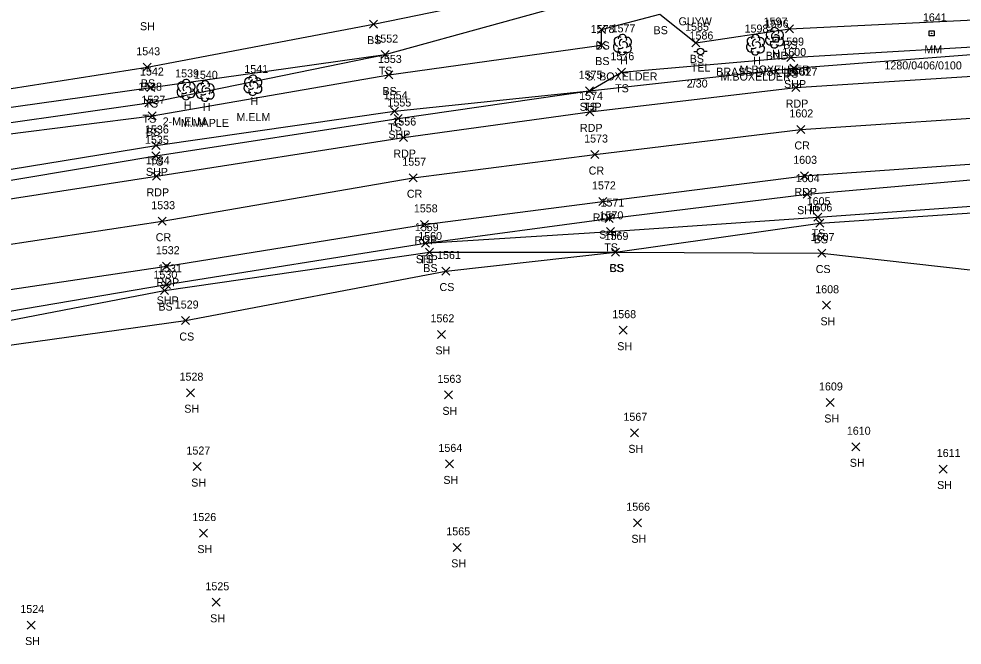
# Model space of a CAD drawing. Extents: x 1497084 to 1499861, y 734741 to 735567.
# Drawn here: x 1499123.3 to 1499358.9, y 735330.7 to 735487.1 of the extents above; entities that cross this region are included whole.
import ezdxf

# ---------------------------------------------------------------- set-up
doc = ezdxf.new("R2010")
doc.units = 0
for name, color, linetype in [('L_A', 7, 'Continuous'), ('L_C', 7, 'Continuous'), ('L_I', 7, 'Continuous'), ('L_TIC', 7, 'Continuous'), ('LELB', 7, 'Continuous'), ('LTD', 7, 'Continuous'), ('M_A', 7, 'Continuous'), ('M_C', 7, 'Continuous'), ('M_I', 7, 'Continuous'), ('MHBP', 7, 'Continuous'), ('P_A', 7, 'Continuous'), ('P_I', 7, 'Continuous'), ('P_TIC', 7, 'Continuous'), ('PET', 7, 'Continuous'), ('PRC', 7, 'Continuous'), ('PSP', 7, 'Continuous'), ('S_A', 7, 'Continuous'), ('S_C', 7, 'Continuous'), ('S_I', 7, 'Continuous'), ('SRM', 7, 'Continuous'), ('U_A', 7, 'Continuous'), ('U_C', 7, 'Continuous'), ('U_I', 7, 'Continuous'), ('UP', 7, 'Continuous')]:
    doc.layers.add(name, color=color, linetype=linetype)

msp = doc.modelspace()

# ---------------------------------------------------------------- linework, layer by layer
at = {"layer": 'L_TIC'}
for points in [[(1499210.81, 735484.81), (1499212.81, 735486.81)], [(1499212.81, 735484.81), (1499210.81, 735486.81)], [(1499267.83, 735483.45), (1499269.83, 735485.45)], [(1499269.83, 735483.45), (1499267.83, 735485.45)], [(1499314.72, 735483.63), (1499316.72, 735485.63)], [(1499316.72, 735483.63), (1499314.72, 735485.63)], [(1499267.79, 735479.58), (1499269.79, 735481.58)], [(1499269.79, 735479.58), (1499267.79, 735481.58)], [(1499291.38, 735480.13), (1499293.38, 735482.13)], [(1499293.38, 735480.13), (1499291.38, 735482.13)], [(1499213.75, 735477.18), (1499215.75, 735479.18)], [(1499215.75, 735477.18), (1499213.75, 735479.18)], [(1499213.75, 735477.18), (1499215.75, 735479.18)], [(1499215.75, 735477.18), (1499213.75, 735479.18)], [(1499315.12, 735476.44), (1499317.12, 735478.44)], [(1499317.12, 735476.44), (1499315.12, 735478.44)], [(1499154.3, 735474.02), (1499156.3, 735476.02)], [(1499156.3, 735474.02), (1499154.3, 735476.02)], [(1499214.64, 735472.1), (1499216.64, 735474.1)], [(1499216.64, 735472.1), (1499214.64, 735474.1)], [(1499272.78, 735472.78), (1499274.78, 735474.78)], [(1499274.78, 735472.78), (1499272.78, 735474.78)], [(1499155.22, 735468.96), (1499157.22, 735470.96)], [(1499157.22, 735468.96), (1499155.22, 735470.96)], [(1499264.79, 735468.16), (1499266.79, 735470.16)], [(1499266.79, 735468.16), (1499264.79, 735470.16)], [(1499154.76, 735465.18), (1499156.76, 735467.18)], [(1499156.76, 735465.18), (1499154.76, 735467.18)], [(1499155.57, 735461.9), (1499157.57, 735463.9)], [(1499157.57, 735461.9), (1499155.57, 735463.9)], [(1499216.09, 735463.03), (1499218.09, 735465.03)], [(1499218.09, 735463.03), (1499216.09, 735465.03)], [(1499156.52, 735454.49), (1499158.52, 735456.49)], [(1499158.52, 735454.49), (1499156.52, 735456.49)], [(1499321.87, 735436.57), (1499323.87, 735438.57)], [(1499323.87, 735436.57), (1499321.87, 735438.57)], [(1499322.36, 735435.06), (1499324.36, 735437.06)], [(1499324.36, 735435.06), (1499322.36, 735437.06)], [(1499270.08, 735433.05), (1499272.08, 735435.05)], [(1499272.08, 735433.05), (1499270.08, 735435.05)], [(1499223.87, 735430.1), (1499225.87, 735432.1)], [(1499225.87, 735430.1), (1499223.87, 735432.1)], [(1499224.84, 735427.89), (1499226.84, 735429.89)], [(1499226.84, 735427.89), (1499224.84, 735429.89)], [(1499271.31, 735427.88), (1499273.31, 735429.88)], [(1499273.31, 735427.88), (1499271.31, 735429.88)], [(1499271.31, 735427.88), (1499273.31, 735429.88)], [(1499273.31, 735427.88), (1499271.31, 735429.88)], [(1499322.85, 735427.64), (1499324.85, 735429.64)], [(1499324.85, 735427.64), (1499322.85, 735429.64)], [(1499228.89, 735423.14), (1499230.89, 735425.14)], [(1499230.89, 735423.14), (1499228.89, 735425.14)], [(1499158.67, 735418.26), (1499160.67, 735420.26)], [(1499160.67, 735418.26), (1499158.67, 735420.26)], [(1499324, 735414.59), (1499326, 735416.59)], [(1499326, 735414.59), (1499324, 735416.59)], [(1499163.91, 735410.78), (1499165.91, 735412.78)], [(1499165.91, 735410.78), (1499163.91, 735412.78)], [(1499273.23, 735408.37), (1499275.23, 735410.37)], [(1499275.23, 735408.37), (1499273.23, 735410.37)], [(1499227.82, 735407.33), (1499229.82, 735409.33)], [(1499229.82, 735407.33), (1499227.82, 735409.33)], [(1499165.1, 735392.76), (1499167.1, 735394.76)], [(1499167.1, 735392.76), (1499165.1, 735394.76)], [(1499229.57, 735392.22), (1499231.57, 735394.22)], [(1499231.57, 735392.22), (1499229.57, 735394.22)], [(1499324.95, 735390.32), (1499326.95, 735392.32)], [(1499326.95, 735390.32), (1499324.95, 735392.32)], [(1499276.01, 735382.74), (1499278.01, 735384.74)], [(1499278.01, 735382.74), (1499276.01, 735384.74)], [(1499331.33, 735379.26), (1499333.33, 735381.26)], [(1499333.33, 735379.26), (1499331.33, 735381.26)], [(1499229.81, 735374.98), (1499231.81, 735376.98)], [(1499231.81, 735374.98), (1499229.81, 735376.98)], [(1499166.83, 735374.32), (1499168.83, 735376.32)], [(1499168.83, 735374.32), (1499166.83, 735376.32)], [(1499353.14, 735373.7), (1499355.14, 735375.7)], [(1499355.14, 735373.7), (1499353.14, 735375.7)], [(1499276.78, 735360.28), (1499278.78, 735362.28)], [(1499278.78, 735360.28), (1499276.78, 735362.28)], [(1499168.36, 735357.71), (1499170.36, 735359.71)], [(1499170.36, 735357.71), (1499168.36, 735359.71)], [(1499231.77, 735354.14), (1499233.77, 735356.14)], [(1499233.77, 735354.14), (1499231.77, 735356.14)], [(1499171.56, 735340.42), (1499173.56, 735342.42)], [(1499173.56, 735340.42), (1499171.56, 735342.42)], [(1499125.34, 735334.75), (1499127.34, 735336.75)], [(1499127.34, 735334.75), (1499125.34, 735336.75)]]:
    msp.add_lwpolyline(points, dxfattribs=at)
at = {"layer": 'LELB'}
for points in [[(1498873.92, 735413.56), (1498885.61, 735419.45), (1498937.6, 735431.47), (1498992.42, 735446.17), (1499046.55, 735456.42), (1499100.05, 735466.4), (1499155.3, 735475.02), (1499211.81, 735485.81), (1499272.89, 735498.35), (1499312.63, 735498.22), (1499378.23, 735496.87), (1499423.72, 735498.7), (1499448.77, 735497.16), (1499468.03, 735503.5), (1499479.61, 735506.38), (1499485.8, 735535.79), (1499495.73, 735555.05)], [(1498887.06, 735413.08), (1498886.64, 735416.64), (1498937.22, 735426.43), (1498992.82, 735439.97), (1499047, 735450.43), (1499100.75, 735458.28), (1499155.76, 735466.18), (1499214.75, 735478.18), (1499272.85, 735494.27), (1499312.36, 735493.24), (1499378.42, 735492.78), (1499423.87, 735493.47), (1499447.7, 735493.36), (1499467.98, 735499.39), (1499480.88, 735502.15), (1499491.75, 735532.72), (1499501.47, 735549.91)], [(1498866.36, 735448.26), (1498857.15, 735430.71), (1498857.91, 735411.98), (1498873.92, 735413.56), (1498887.06, 735413.08), (1498937.75, 735422.9), (1498993.01, 735435.64), (1499049.83, 735446.27), (1499101.27, 735455.9), (1499156.57, 735462.9), (1499215.64, 735473.1), (1499268.79, 735480.58), (1499268.83, 735484.45), (1499283.35, 735488.28), (1499292.38, 735481.13), (1499315.72, 735484.63), (1499378.98, 735487.71)], [(1498836.02, 735409.82), (1498851.62, 735410.69), (1498873.71, 735408.53), (1498887.41, 735411.13), (1498937.88, 735419.58), (1498994.04, 735428.91), (1499054.48, 735438.88), (1499102.91, 735446.6), (1499157.52, 735455.49), (1499217.09, 735464.03), (1499265.79, 735469.16), (1499273.78, 735473.78), (1499316.12, 735477.44), (1499378.42, 735481.09), (1499425.85, 735484.53), (1499445.24, 735487.28), (1499459.87, 735483.77), (1499494.5, 735481.39), (1499511.88, 735480.66), (1499514.4, 735477.39)], [(1498937.22, 735426.43), (1498937.39, 735427.9), (1498992.7, 735442.42), (1499047.14, 735453.13), (1499100.52, 735462.11), (1499156.22, 735469.96), (1499214.75, 735478.18)], [(1498902.07, 735368.05), (1498907.17, 735371.51), (1498940.32, 735377.55), (1498999.63, 735387.02), (1499017.69, 735389.23), (1499022.6, 735383.12), (1499048.5, 735392.29), (1499056.36, 735395.92), (1499109.05, 735409.57), (1499159.67, 735419.26), (1499225.84, 735428.89), (1499272.31, 735428.88), (1499323.36, 735436.06), (1499376.02, 735439.69), (1499385.74, 735428.35), (1499408.33, 735432.03), (1499419.24, 735438.19), (1499448.18, 735438.04), (1499493.15, 735436.77), (1499505.9, 735439.37), (1499516.74, 735441.77), (1499516.38, 735446.4), (1499513.83, 735450.64)], [(1499224.87, 735431.1), (1499271.08, 735434.05), (1499322.87, 735437.57), (1499384.48, 735442.03), (1499412.03, 735442.18), (1499420.22, 735445.71), (1499447.12, 735442.74), (1499493.29, 735444.7), (1499504.12, 735447.13), (1499512.27, 735451.02)], [(1499047.27, 735383.52), (1499066.78, 735390.4), (1499110.69, 735404.23), (1499164.91, 735411.78), (1499229.89, 735424.14), (1499272.31, 735428.88), (1499323.85, 735428.64), (1499384.64, 735421.78), (1499405.49, 735421.31)]]:
    msp.add_lwpolyline(points, dxfattribs=at)
at = {"layer": 'LTD'}
for p, q in [((1499274, 735480.74), (1499274, 735480.74)), ((1499274, 735480.74), (1499274, 735480.74)), ((1499307.22, 735480.69), (1499307.22, 735480.69)), ((1499307.22, 735480.69), (1499307.22, 735480.69)), ((1499311.99, 735482.45), (1499311.99, 735482.45)), ((1499311.99, 735482.45), (1499311.99, 735482.45)), ((1499165, 735469.5), (1499165, 735469.5)), ((1499165, 735469.5), (1499165, 735469.5)), ((1499169.77, 735469.14), (1499169.77, 735469.14)), ((1499169.77, 735469.14), (1499169.77, 735469.14)), ((1499181.71, 735470.59), (1499181.71, 735470.59)), ((1499181.71, 735470.59), (1499181.71, 735470.59))]:
    msp.add_line(p, q, dxfattribs=at)
for centre in [(1499274.04, 735482.17), (1499307.27, 735482.12), (1499312.04, 735483.88), (1499165.05, 735470.93), (1499169.82, 735470.58), (1499181.75, 735472.02)]:
    msp.add_arc(centre, 1.05, 335.5272, 180.9563, dxfattribs=at)
for centre, major_axis, ratio, start_param, end_param in [((1499273.21, 735481.41), (1.21, -0.51), 0.895232, 1.570796, 4.712389), ((1499275.04, 735481.32), (-1.14, -0.48), 0.949671, 1.570796, 4.712389), ((1499306.43, 735481.35), (1.21, -0.51), 0.895232, 1.570796, 4.712389), ((1499310.91, 735481.74), (0.58, -1.04), 0.959034, 3.141593, 6.283185), ((1499311.2, 735483.11), (1.21, -0.51), 0.895232, 1.570796, 4.712389), ((1499311.79, 735482.91), (-0.208, -0.792), 0.645439, 3.141593, 6.283185), ((1499312.49, 735482.28), (-0.5, 0.667), 0.989748, 3.141593, 6.283185), ((1499313.04, 735483.03), (-1.14, -0.48), 0.949671, 1.570796, 4.712389), ((1499272.91, 735480.03), (0.58, -1.04), 0.959034, 3.141593, 6.283185), ((1499273.79, 735481.2), (-0.208, -0.792), 0.645439, 3.141593, 6.283185), ((1499274.5, 735480.57), (-0.5, 0.667), 0.989748, 3.141593, 6.283185), ((1499275, 735479.91), (-1.09, 0.79), 0.841452, 1.570796, 4.712389), ((1499306.14, 735479.98), (0.58, -1.04), 0.959034, 3.141593, 6.283185), ((1499307.02, 735481.14), (-0.208, -0.792), 0.645439, 3.141593, 6.283185), ((1499307.72, 735480.52), (-0.5, 0.667), 0.989748, 3.141593, 6.283185), ((1499308.23, 735479.85), (-1.09, 0.79), 0.841452, 1.570796, 4.712389), ((1499308.27, 735481.27), (-1.14, -0.48), 0.949671, 1.570796, 4.712389), ((1499311.99, 735480.95), (0.26, 1.06), 0.942809, 1.570796, 4.712389), ((1499311.54, 735481.7), (-0.625, -0.083), 0.423636, 0, 3.141593), ((1499312.99, 735481.61), (-1.09, 0.79), 0.841452, 1.570796, 4.712389), ((1499274, 735479.24), (0.26, 1.06), 0.942809, 1.570796, 4.712389), ((1499273.54, 735479.99), (-0.625, -0.083), 0.423636, 0, 3.141593), ((1499307.23, 735479.19), (0.26, 1.06), 0.942809, 1.570796, 4.712389), ((1499306.77, 735479.94), (-0.625, -0.083), 0.423636, 0, 3.141593), ((1499164.21, 735470.17), (1.21, -0.51), 0.895232, 1.570796, 4.712389), ((1499166.05, 735470.08), (-1.14, -0.48), 0.949671, 1.570796, 4.712389), ((1499168.98, 735469.81), (1.21, -0.51), 0.895232, 1.570796, 4.712389), ((1499170.81, 735469.73), (-1.14, -0.48), 0.949671, 1.570796, 4.712389), ((1499180.62, 735469.88), (0.58, -1.04), 0.959034, 3.141593, 6.283185), ((1499180.91, 735471.26), (1.21, -0.51), 0.895232, 1.570796, 4.712389), ((1499181.5, 735471.05), (-0.208, -0.792), 0.645439, 3.141593, 6.283185), ((1499182.21, 735470.42), (-0.5, 0.667), 0.989748, 3.141593, 6.283185), ((1499182.75, 735471.17), (-1.14, -0.48), 0.949671, 1.570796, 4.712389), ((1499163.92, 735468.79), (0.58, -1.04), 0.959034, 3.141593, 6.283185), ((1499164.55, 735468.75), (-0.625, -0.083), 0.423636, 0, 3.141593), ((1499164.8, 735469.96), (-0.208, -0.792), 0.645439, 3.141593, 6.283185), ((1499165.5, 735469.33), (-0.5, 0.667), 0.989748, 3.141593, 6.283185), ((1499166, 735468.67), (-1.09, 0.79), 0.841452, 1.570796, 4.712389), ((1499168.69, 735468.43), (0.58, -1.04), 0.959034, 3.141593, 6.283185), ((1499169.56, 735469.6), (-0.208, -0.792), 0.645439, 3.141593, 6.283185), ((1499170.27, 735468.98), (-0.5, 0.667), 0.989748, 3.141593, 6.283185), ((1499170.77, 735468.31), (-1.09, 0.79), 0.841452, 1.570796, 4.712389), ((1499181.71, 735469.09), (0.26, 1.06), 0.942809, 1.570796, 4.712389), ((1499181.25, 735469.84), (-0.625, -0.083), 0.423636, 0, 3.141593), ((1499182.71, 735469.76), (-1.09, 0.79), 0.841452, 1.570796, 4.712389), ((1499165, 735468), (0.26, 1.06), 0.942809, 1.570796, 4.712389), ((1499169.77, 735467.64), (0.26, 1.06), 0.942809, 1.570796, 4.712389), ((1499169.31, 735468.39), (-0.625, -0.083), 0.423636, 0, 3.141593)]:
    msp.add_ellipse(centre, major_axis=major_axis, ratio=ratio, start_param=start_param, end_param=end_param, dxfattribs=at)
at = {"layer": 'MHBP'}
msp.add_lwpolyline([(1499311.7, 735482.53), (1499312.95, 735482.53), (1499312.95, 735481.28), (1499311.7, 735481.28)], close=True, dxfattribs=at)
msp.add_circle((1499312.32, 735481.91), 0.0833, dxfattribs=at)
at = {"layer": 'P_TIC'}
for points in [[(1499315.87, 735473.83), (1499317.87, 735475.83)], [(1499317.87, 735473.83), (1499315.87, 735475.83)], [(1499316.31, 735468.95), (1499318.31, 735470.95)], [(1499318.31, 735468.95), (1499316.31, 735470.95)], [(1499264.79, 735468.16), (1499266.79, 735470.16)], [(1499266.79, 735468.16), (1499264.79, 735470.16)], [(1499264.92, 735462.89), (1499266.92, 735464.89)], [(1499266.92, 735462.89), (1499264.92, 735464.89)], [(1499217.03, 735461.22), (1499219.03, 735463.22)], [(1499219.03, 735461.22), (1499217.03, 735463.22)], [(1499317.55, 735458.5), (1499319.55, 735460.5)], [(1499319.55, 735458.5), (1499317.55, 735460.5)], [(1499218.31, 735456.47), (1499220.31, 735458.47)], [(1499220.31, 735456.47), (1499218.31, 735458.47)], [(1499156.46, 735451.91), (1499158.46, 735453.91)], [(1499158.46, 735451.91), (1499156.46, 735453.91)], [(1499266.15, 735452.23), (1499268.15, 735454.23)], [(1499268.15, 735452.23), (1499266.15, 735454.23)], [(1499156.66, 735446.8), (1499158.66, 735448.8)], [(1499158.66, 735446.8), (1499156.66, 735448.8)], [(1499220.74, 735446.44), (1499222.74, 735448.44)], [(1499222.74, 735446.44), (1499220.74, 735448.44)], [(1499318.5, 735446.91), (1499320.5, 735448.91)], [(1499320.5, 735446.91), (1499318.5, 735448.91)], [(1499319.13, 735442.34), (1499321.13, 735444.34)], [(1499321.13, 735442.34), (1499319.13, 735444.34)], [(1499268.11, 735440.52), (1499270.11, 735442.52)], [(1499270.11, 735440.52), (1499268.11, 735442.52)], [(1499269.68, 735436.25), (1499271.68, 735438.25)], [(1499271.68, 735436.25), (1499269.68, 735438.25)], [(1499158.02, 735435.58), (1499160.02, 735437.58)], [(1499160.02, 735435.58), (1499158.02, 735437.58)], [(1499223.61, 735434.78), (1499225.61, 735436.78)], [(1499225.61, 735434.78), (1499223.61, 735436.78)], [(1499223.87, 735430.1), (1499225.87, 735432.1)], [(1499225.87, 735430.1), (1499223.87, 735432.1)], [(1499159.18, 735424.34), (1499161.18, 735426.34)], [(1499161.18, 735424.34), (1499159.18, 735426.34)], [(1499159.14, 735419.81), (1499161.14, 735421.81)], [(1499161.14, 735419.81), (1499159.14, 735421.81)]]:
    msp.add_lwpolyline(points, dxfattribs=at)
at = {"layer": 'PET'}
for points in [[(1498838.32, 735395.91), (1498888.99, 735404.3), (1498938.22, 735411.59), (1498994.69, 735421.68), (1499054.78, 735430.96), (1499104.38, 735439.6), (1499157.66, 735447.8), (1499219.31, 735457.47), (1499265.92, 735463.89), (1499317.31, 735469.95), (1499378.29, 735473.92), (1499424.75, 735475.7), (1499462.5, 735476.09), (1499495.09, 735475.96), (1499513.91, 735475.18)], [(1498842.44, 735373.21), (1498892.67, 735381.87), (1498940.26, 735389.17), (1498997.67, 735398.94), (1499056.44, 735408.41), (1499108.2, 735417.59), (1499160.18, 735425.34), (1499224.61, 735435.78), (1499269.11, 735441.52), (1499319.5, 735447.91), (1499378.39, 735452.04), (1499424.16, 735454.42), (1499461.26, 735454.74), (1499493.51, 735454.63), (1499512.44, 735453.4), (1499513.2, 735464.25), (1499513.91, 735475.18)]]:
    msp.add_lwpolyline(points, dxfattribs=at)
at = {"layer": 'PRC'}
msp.add_lwpolyline([(1498839.89, 735384.37), (1498890.74, 735392.79), (1498939.31, 735400.24), (1498995.85, 735410.01), (1499056.08, 735419.64), (1499106.34, 735428.63), (1499159.02, 735436.58), (1499221.74, 735447.44), (1499267.15, 735453.23), (1499318.55, 735459.5), (1499378.61, 735463.51), (1499424.29, 735465.34), (1499461.73, 735465.4), (1499494.05, 735465.28), (1499513.2, 735464.25)], dxfattribs=at)
at = {"layer": 'PSP'}
for points in [[(1498833.8, 735399.85), (1498855.6, 735403.69), (1498873.7, 735405.84), (1498888.17, 735408.98), (1498937.73, 735416.37), (1498993.87, 735425.67), (1499054.79, 735435.66), (1499103.37, 735443.86), (1499157.46, 735452.91), (1499218.03, 735462.22), (1499265.79, 735469.16), (1499316.87, 735474.83), (1499378.34, 735479.55), (1499425.23, 735479.95), (1499462.88, 735477.81), (1499495.09, 735475.96)], [(1498843.61, 735368.57), (1498860.46, 735371.23), (1498865.28, 735372.42), (1498905.37, 735378.8), (1498940.19, 735384.06), (1498998.48, 735394.31), (1499018.85, 735397.58), (1499054.41, 735403.83), (1499108.72, 735412.03), (1499160.14, 735420.81), (1499224.87, 735431.1), (1499270.68, 735437.25), (1499320.13, 735443.34), (1499381.94, 735448.71), (1499417.25, 735450.68), (1499461.26, 735454.74)]]:
    msp.add_lwpolyline(points, dxfattribs=at)
at = {"layer": 'SRM'}
msp.add_lwpolyline([(1499350.62, 735484.12), (1499351.87, 735484.12), (1499351.87, 735482.87), (1499350.62, 735482.87)], close=True, dxfattribs=at)
msp.add_circle((1499351.24, 735483.49), 0.0833, dxfattribs=at)
at = {"layer": 'UP'}
for p, q in [((1499291.87, 735478.95), (1499292.7, 735478.95)), ((1499293.53, 735478.96), (1499293.53, 735478.96)), ((1499295.2, 735478.96), (1499294.36, 735478.96)), ((1499294.36, 735478.96), (1499294.36, 735478.96)), ((1499295.2, 735478.96), (1499295.2, 735478.96))]:
    msp.add_line(p, q, dxfattribs=at)
msp.add_circle((1499293.53, 735478.96), 0.833, dxfattribs=at)

# ---------------------------------------------------------------- texts
at = {"layer": 'L_A'}
for s, p in [('SH', (1499153.52, 735484.27)), ('BS', (1499281.79, 735483.28)), ('BS', (1499210.25, 735480.81)), ('BS', (1499267.28, 735479.45)), ('BS', (1499314.16, 735479.63)), ('BS', (1499290.82, 735476.13)), ('H', (1499311.43, 735477.45)), ('BS', (1499267.23, 735475.58)), ('H', (1499273.43, 735475.74)), ('H', (1499306.66, 735475.69)), ('TS', (1499213.16, 735473.18)), ('TS', (1499213.16, 735473.18)), ('TS', (1499314.53, 735472.44)), ('BS', (1499153.74, 735470.02)), ('BS', (1499214.08, 735468.1)), ('TS', (1499272.19, 735468.78)), ('TS', (1499154.63, 735464.96)), ('H', (1499164.44, 735464.5)), ('H', (1499181.14, 735465.59)), ('TS', (1499264.2, 735464.16)), ('H', (1499169.2, 735464.14)), ('TS', (1499154.17, 735461.18)), ('BS', (1499155.01, 735457.9)), ('TS', (1499215.5, 735459.03)), ('TS', (1499155.93, 735450.49)), ('TS', (1499321.28, 735432.57)), ('TS', (1499269.49, 735429.05)), ('BS', (1499321.8, 735431.06)), ('TS', (1499223.28, 735426.1)), ('BS', (1499224.28, 735423.89)), ('CS', (1499270.75, 735423.88)), ('BS', (1499270.75, 735423.88)), ('CS', (1499322.3, 735423.64)), ('CS', (1499228.33, 735419.14)), ('BS', (1499158.11, 735414.26)), ('SH', (1499323.48, 735410.59)), ('CS', (1499163.35, 735406.78)), ('SH', (1499227.31, 735403.33)), ('SH', (1499272.72, 735404.37)), ('SH', (1499164.58, 735388.76)), ('SH', (1499229.06, 735388.22)), ('SH', (1499324.44, 735386.32)), ('SH', (1499275.5, 735378.74)), ('SH', (1499330.82, 735375.26)), ('SH', (1499166.31, 735370.32)), ('SH', (1499229.3, 735370.98)), ('SH', (1499352.63, 735369.7)), ('SH', (1499276.27, 735356.28)), ('SH', (1499167.85, 735353.71)), ('SH', (1499231.26, 735350.14)), ('SH', (1499171.05, 735336.42)), ('SH', (1499124.82, 735330.75))]:
    msp.add_text(s, height=2, dxfattribs=at).set_placement(p)
at = {"layer": 'L_C'}
for s, p in [('S. BOXELDER', (1499264.93, 735471.74)), ('M.BOXELDER', (1499298.52, 735471.69)), ('M.BOXELDER', (1499303.29, 735473.45)), ('2-M.ELM', (1499159.19, 735460.5)), ('M.MAPLE', (1499163.71, 735460.14)), ('M.ELM', (1499177.61, 735461.59))]:
    msp.add_text(s, height=2, dxfattribs=at).set_placement(p)
at = {"layer": 'L_I'}
for s, p in [('1597', (1499309.3, 735485.45)), ('1578', (1499266.1, 735483.58)), ('1577', (1499271.31, 735483.74)), ('1585', (1499289.68, 735484.13)), ('1598', (1499304.53, 735483.69)), ('1552', (1499212.06, 735481.18)), ('1552', (1499212.06, 735481.18)), ('1599', (1499313.42, 735480.44)), ('1543', (1499152.6, 735478.02)), ('1553', (1499212.95, 735476.1)), ('1576', (1499271.03, 735476.78)), ('1542', (1499153.52, 735472.96)), ('1539', (1499162.3, 735472.5)), ('1540', (1499166.99, 735472.14)), ('1541', (1499179.58, 735473.59)), ('1575', (1499263.1, 735472.16)), ('1538', (1499153.06, 735469.18)), ('1554', (1499214.4, 735467.03)), ('1537', (1499153.88, 735465.9)), ('1536', (1499154.77, 735458.49)), ('1605', (1499320.05, 735440.57)), ('1606', (1499320.49, 735439.06)), ('1570', (1499268.3, 735437.05)), ('1559', (1499222.17, 735434.1)), ('1560', (1499223.01, 735431.89)), ('1569', (1499269.56, 735431.88)), ('1569', (1499269.56, 735431.88)), ('1607', (1499321.04, 735431.64)), ('1561', (1499227.72, 735427.14)), ('1530', (1499156.89, 735422.26)), ('1608', (1499322.18, 735418.59)), ('1529', (1499162.21, 735414.78)), ('1568', (1499271.49, 735412.37)), ('1562', (1499226.08, 735411.33)), ('1528', (1499163.4, 735396.76)), ('1563', (1499227.83, 735396.22)), ('1609', (1499323.12, 735394.32)), ('1567', (1499274.27, 735386.74)), ('1610', (1499330.07, 735383.26)), ('1527', (1499165.13, 735378.32)), ('1564', (1499228.07, 735378.98)), ('1611', (1499352.53, 735377.7)), ('1566', (1499274.98, 735364.28)), ('1526', (1499166.61, 735361.71)), ('1565', (1499230.03, 735358.14)), ('1525', (1499169.87, 735344.42)), ('1524', (1499123.64, 735338.75))]:
    msp.add_text(s, height=2, dxfattribs=at).set_placement(p)
at = {"layer": 'M_A'}
msp.add_text('BND', height=2, dxfattribs=at).set_placement((1499309.81, 735476.91))
at = {"layer": 'M_C'}
msp.add_text('BRASS DISK LS 527', height=2, dxfattribs=at).set_placement((1499297.46, 735472.91))
at = {"layer": 'M_I'}
msp.add_text('1596', height=2, dxfattribs=at).set_placement((1499309.57, 735484.91))
at = {"layer": 'P_A'}
for s, p in [('SHP', (1499314.4, 735469.83)), ('SHP', (1499263.33, 735464.16)), ('RDP', (1499314.8, 735464.95)), ('SHP', (1499215.56, 735457.22)), ('RDP', (1499263.41, 735458.89)), ('RDP', (1499216.8, 735452.47)), ('CR', (1499316.98, 735454.5)), ('SHP', (1499155, 735447.91)), ('CR', (1499265.58, 735448.23)), ('RDP', (1499155.15, 735442.8)), ('CR', (1499220.18, 735442.44)), ('RDP', (1499316.99, 735442.91)), ('SHP', (1499317.66, 735438.34)), ('RDP', (1499266.6, 735436.52)), ('CR', (1499157.45, 735431.58)), ('SHP', (1499268.21, 735432.25)), ('RDP', (1499222.1, 735430.78)), ('SHP', (1499222.41, 735426.1)), ('RDP', (1499157.66, 735420.34)), ('SHP', (1499157.68, 735415.81))]:
    msp.add_text(s, height=2, dxfattribs=at).set_placement(p)
at = {"layer": 'P_I'}
for s, p in [('1600', (1499313.96, 735477.83)), ('1575', (1499263.1, 735472.16)), ('1601', (1499315.06, 735472.95)), ('1574', (1499263.22, 735466.89)), ('1555', (1499215.33, 735465.22)), ('1602', (1499315.73, 735462.5)), ('1556', (1499216.56, 735460.47)), ('1535', (1499154.77, 735455.91)), ('1573', (1499264.46, 735456.23)), ('1534', (1499154.97, 735450.8)), ('1557', (1499219.05, 735450.44)), ('1603', (1499316.68, 735450.91)), ('1604', (1499317.31, 735446.34)), ('1572', (1499266.42, 735444.52)), ('1533', (1499156.33, 735439.58)), ('1558', (1499221.92, 735438.78)), ('1571', (1499268.55, 735440.25)), ('1559', (1499222.17, 735434.1)), ('1532', (1499157.48, 735428.34)), ('1531', (1499158.02, 735423.81))]:
    msp.add_text(s, height=2, dxfattribs=at).set_placement(p)
at = {"layer": 'S_A'}
msp.add_text('MM', height=2, dxfattribs=at).set_placement((1499349.43, 735478.49))
at = {"layer": 'S_C'}
msp.add_text('1280/0406/0100', height=2, dxfattribs=at).set_placement((1499339.46, 735474.49))
at = {"layer": 'S_I'}
msp.add_text('1641', height=2, dxfattribs=at).set_placement((1499349.07, 735486.49))
at = {"layer": 'U_A'}
for s, p in [('GUYW', (1499288.04, 735485.5)), ('TEL', (1499291.09, 735473.96))]:
    msp.add_text(s, height=2, dxfattribs=at).set_placement(p)
at = {"layer": 'U_C'}
msp.add_text('2/30', height=2, dxfattribs=at).set_placement((1499290.1, 735469.96))
at = {"layer": 'U_I'}
msp.add_text('1586', height=2, dxfattribs=at).set_placement((1499290.78, 735481.96))

doc.saveas('drawing.dxf')
